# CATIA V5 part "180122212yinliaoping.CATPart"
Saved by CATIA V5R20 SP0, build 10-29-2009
Part number: 饮料瓶
Material "无"
Material "Plastic": density 1200 kg/m3, Young's modulus 2.2e+09 Pa, Poisson ratio 0.38, thermal expansion 6.84e-05 1/K
Material "Plastic": density 1200 kg/m3, Young's modulus 2.2e+09 Pa, Poisson ratio 0.38, thermal expansion 6.84e-05 1/K
Material "Plastic": density 1200 kg/m3, Young's modulus 2.2e+09 Pa, Poisson ratio 0.38, thermal expansion 6.84e-05 1/K
Material "DS star": density 1000 kg/m3
Bounding box of the stored display mesh (mm): x -25 to 25, y -25 to 25.2, z 0 to 110
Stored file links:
  G:\yinliaoping180122212.CATPart
  D:\Catia\win_b64\startup\materials\Catalog.CATMaterial
  D:\Catia\win_b64\startup\materials\DS_star.jpg
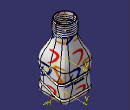
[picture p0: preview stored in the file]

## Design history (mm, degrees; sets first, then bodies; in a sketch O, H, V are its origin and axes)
Set1, material "Plastic"
  Sketch1 on xy-plane, origin (0, 0, 0), H (1, 0, 0), V (0, 1, 0)
    line L1 (25, 25) -> (25, -25)
    line L2 (25, -25) -> (-25, -25)
    line L3 (-25, -25) -> (-25, 25)
    line L4 (-25, 25) -> (25, 25)
    length L1 = 50
    length L2 = 50
    vertical: L1 V, L3 V
    horizontal: L2 H, L4 H
    equidistance: L1 L3 O, L2 L4 O
  Sketch2 on face of Pad1 from Sketch1.L1, origin (25, 0, 0), H (0, 1, 0), V (0, 0, 1)
    spline S1 through (-40, 10) (-20, 20) (10, 10) (40, 20)
  Extrude1: Element1 Sketch2, Lim1 -60, Lim2 0
  MultiSel1: CommonCtxFeats ({extract ExtractElem face of Pad1 from Sketch1.L1}; {extract ExtractElem face of Fillet1}; {extract ExtractElem face of Pad1 from Sketch1.L4}; {extract ExtractElem face of Fillet1}; {extract ExtractElem face of Pad1 from Sketch1.L3}; {extract ExtractElem face of Fillet1}; {extract ExtractElem face of Pad1 from Sketch1.L2}; {extract ExtractElem face of Fillet1})
  Join1: Elements ({intersect ToIntersect1 {extract ExtractElem face of Pad1 from Sketch1.L1}, ToIntersect2 Extrude1}; {intersect ToIntersect1 {extract ExtractElem face of Fillet1}, ToIntersect2 Extrude1}; {intersect ToIntersect1 {extract ExtractElem face of Fillet1}, ToIntersect2 Extrude1}; {intersect ToIntersect1 {extract ExtractElem face of Pad1 from Sketch1.L4}, ToIntersect2 Extrude1}; {intersect ToIntersect1 {extract ExtractElem face of Pad1 from Sketch1.L3}, ToIntersect2 Extrude1}; {intersect ToIntersect1 {extract ExtractElem face of Fillet1}, ToIntersect2 Extrude1}; {intersect ToIntersect1 {extract ExtractElem face of Pad1 from Sketch1.L2}, ToIntersect2 Extrude1}; {intersect ToIntersect1 {extract ExtractElem face of Fillet1}, ToIntersect2 Extrude1})
  Sketch3 on face of Pad1 from Sketch1.L1, origin (25, 0, 0), H (0, 1, 0), V (0, 0, 1)
    spline S1 through (-40, 30) (-20, 40) (10, 30) (30, 40)
  Extrude2: Element1 Sketch3, Lim1 -60, Lim2 0
  MultiSel2: CommonCtxFeats ({extract ExtractElem face of Pad1 from Sketch1.L4}; {extract ExtractElem face of Fillet1}; {extract ExtractElem face of Pad1 from Sketch1.L3}; {extract ExtractElem face of Fillet1}; {extract ExtractElem face of Pad1 from Sketch1.L1}; {extract ExtractElem face of Fillet1}; {extract ExtractElem face of Pad1 from Sketch1.L2}; {extract ExtractElem face of Fillet1})
  Join2: Elements ({intersect ToIntersect1 {extract ExtractElem face of Pad1 from Sketch1.L1}, ToIntersect2 Extrude2}; {intersect ToIntersect1 {extract ExtractElem face of Fillet1}, ToIntersect2 Extrude2}; {intersect ToIntersect1 {extract ExtractElem face of Pad1 from Sketch1.L2}, ToIntersect2 Extrude2}; {intersect ToIntersect1 {extract ExtractElem face of Fillet1}, ToIntersect2 Extrude2}; {intersect ToIntersect1 {extract ExtractElem face of Pad1 from Sketch1.L3}, ToIntersect2 Extrude2}; {intersect ToIntersect1 {extract ExtractElem face of Fillet1}, ToIntersect2 Extrude2}; {intersect ToIntersect1 {extract ExtractElem face of Pad1 from Sketch1.L4}, ToIntersect2 Extrude2}; {intersect ToIntersect1 {extract ExtractElem face of Fillet1}, ToIntersect2 Extrude2})
  Plane1: type Normal, Curve Join2, RefPoint vertex [face of MultiSel2 | face of MultiSel2]
  Sketch4 on Plane1, origin (0, -24.5328, 6.3124), H (-1, 0, 0), V (0, 0.2492, 0.9685)
    circle A1 centre (25, 34.0479) radius 2
    point P1 (25, 34.0479)
    reference projected point E1 (25, 34.0479) from vertex [face of MultiSel2 | face of MultiSel2]
    coincidence: E1 P1
  Plane2: type Normal, Curve Join1, RefPoint vertex [face of MultiSel1 | face of MultiSel1]
  Sketch5 on Plane2, origin (0, -16.4382, 5.1053), H (-1, 0, 0), V (0, 0.2966, 0.955)
    circle A1 centre (25, 14.0849) radius 2
    point P1 (25, 14.0849)
    reference projected point E1 (25, 14.0849) from vertex [face of MultiSel1 | face of MultiSel1]
    coincidence: E1 P1
Body1 (main body), material "DS star"
  Pad1: profile Sketch1, direction (0, 0, 1), length 50
  Fillet1: on edge [face of Pad1 from Sketch1.L4 | face of Pad1 from Sketch1.L1]; edge [face of Pad1 from Sketch1.L3 | face of Pad1 from Sketch1.L4]; edge [face of Pad1 from Sketch1.L1 | face of Pad1 from Sketch1.L2]; edge [face of Pad1 from Sketch1.L2 | face of Pad1 from Sketch1.L3]
  Plane3: type Offset, RefPlane xy-plane, Offset 90
  Sketch6 on Plane3, origin (0, 0, 90), H (1, 0, 0), V (0, 1, 0)
    circle A1 centre (0, 0) radius 15
    point P1 (15, 0)
    coincidence: A1 P1, P1 H
  Pad2: profile Sketch6, direction (0, 0, 1), length 20
  Fillet2: on edge [start face of Pad1 | face of Pad1 from Sketch1.L3]
  Sketch7 on end face of Pad1, origin (0, 0, 50), H (1, 0, 0), V (0, 1, 0)
    point P1 (25, 0)
    distance P1 V = 25
    coincidence: P1 H
  Sketch8 on end face of Pad1, origin (0, 0, 50), H (1, 0, 0), V (0, 1, 0)
  Sketch9 on start face of Pad2, origin (0, 0, 90), H (1, 0, 0), V (0, -1, 0)
    point P1 (15, 0)
    distance P1 V = 15
    coincidence: P1 H
  Loft1: solid, Sections ({boundary Boundary {extract ExtractElem start face of Pad2}}; {boundary Boundary {extract ExtractElem end face of Pad1}}), StartFace start face of Pad2, EndFace end face of Pad1
  Slot1: profile Sketch4, centre curve Join2
  Slot2: profile Sketch5, centre curve Join1
  Shell1: IntOffset 1, Face end face of Pad2, ExtOffset 0
  Sketch10 on xy-plane, origin (0, 0, 0), H (1, 0, 0), V (0, 1, 0)
    point P1 (15, 0)
    coincidence: P1 H
  Point1: (0, 0, 2), relative to Sketch9
  Helix1: Direction Z axis, RefPoint Point1, Pitch 3, Height 16, TaperAngle 0
  Body2
  Remove1: tool Body2
  Plane4: type 2Lines, Element1 Sketch6.V, Element2 Sketch6.H
Body3
  Sketch11 on face of Pad1 from Sketch1.L4, origin (0, 25, 0), H (-1, 0, 0), V (0, 0, 1)
    polyline C1
    polyline C2
    polyline C3
    polyline C4
    polyline C5
    polyline C6
    polyline C7
    polyline C8
    polyline C9
    polyline C10
    polyline C11
    polyline C12
    polyline C13
  Pad3: profile Sketch11, direction (0, 1, 0), length 0.2
  Point2: type OnCurve, Support Helix1, RefPoint Point1, Length 6
  Point3: type OnCurve, Support Helix1, RefPoint vertex of Helix1, Length -6
  Line1: type Normal, RefPoint vertex of Helix1, RefSkin face of Pad2 from Sketch6.A1, Start 0, End 10
  Line2: type Normal, RefPoint Point1, RefSkin face of Pad2 from Sketch6.A1, Start 0, End 10
  Connect1: Curve1 Line1, Point1 vertex of Line1, Tension1 1, Curve2 Helix1, Point2 Point3, Tension2 1
  Connect2: Curve1 Line2, Point1 vertex of Line2, Tension1 1, Curve2 Connect1, Point2 Point2, Tension2 1
  Plane5: type Normal, Curve Connect2, RefPoint Point2
  Sketch12 on Plane5, origin (-1.1411, 2.7004, 0.0933), H (0.9211, 0.3892, 0), V (0.0124, -0.0293, 0.9995)
    circle A1 centre (15, 92.1442) radius 1
    point P1 (15, 92.1442)
    reference projected point E1 (15, 92.1442) from Point2
    coincidence: P1 E1
  Rib1: profile Sketch12, centre curve Connect2
  Body4
    Sketch13 on Plane4, origin (0, 0, 90), H (1, 0, 0), V (0, -1, 0)
      circle A1 centre (0, 0) radius 14
    Pad4: profile Sketch13, direction (0, 0, 1), length 22
  Remove2: tool Body4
